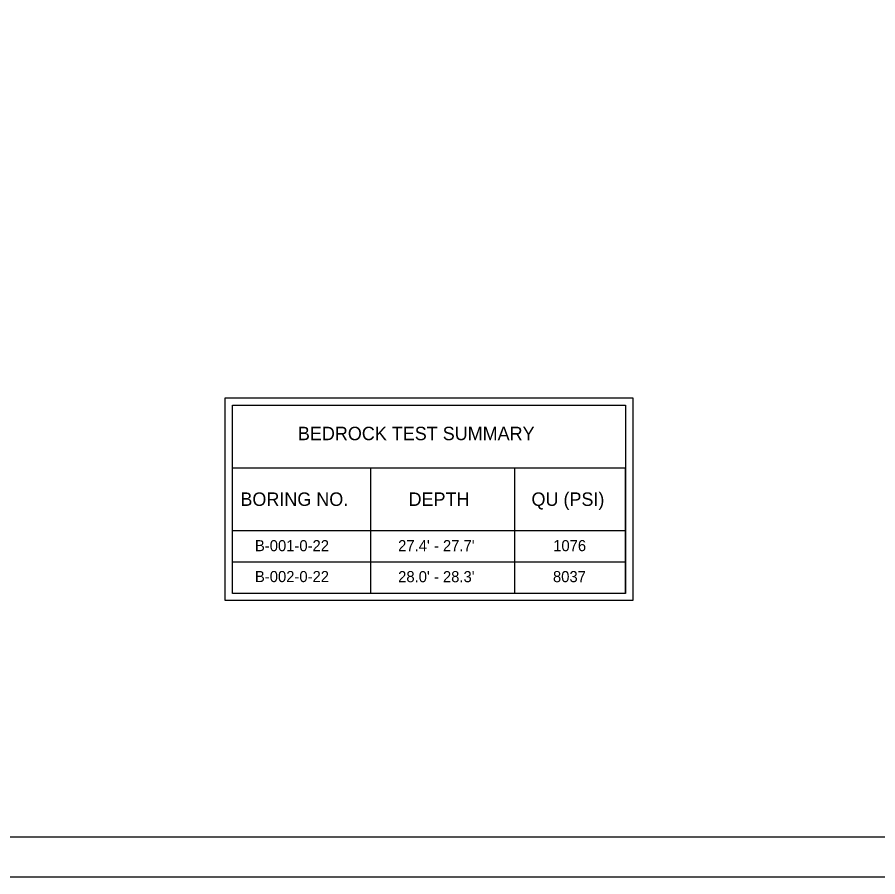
# Model space of a CAD drawing. Extents: x -60 to 375, y -195 to 44.
# Drawn here: x 6.18 to 11.62, y 0.02 to 5.46 of the extents above; entities that cross this region are included whole.
import ezdxf

# ---------------------------------------------------------------- set-up
doc = ezdxf.new("R2010")
doc.units = 0
for name, color, linetype in [('GM_X_County', 7, 'Continuous'), ('GM_X_County_Road_Text', 7, 'Continuous'), ('GM_X_Township_Road_Text', 7, 'Continuous')]:
    doc.layers.add(name, color=color, linetype=linetype)

msp = doc.modelspace()

# ---------------------------------------------------------------- linework, layer by layer
at = {"layer": 'GM_X_County'}
for p, q in [((7.4963, 3.0525), (10.0744, 3.0525)), ((7.4963, 1.7709), (7.4963, 3.0525)), ((10.0744, 3.0525), (10.0744, 1.7709)), ((7.5419, 3.0069), (10.0288, 3.0069)), ((7.5419, 1.8165), (7.5419, 3.0069)), ((10.0288, 3.0069), (10.0288, 1.8165)), ((7.5419, 2.6105), (10.0288, 2.6105)), ((8.4183, 1.8165), (8.4183, 2.6105)), ((8.4183, 1.8165), (8.4183, 2.6105)), ((9.3274, 1.8165), (9.3274, 2.6105)), ((10.0288, 1.8165), (10.0288, 2.6105)), ((7.5419, 2.2141), (10.0288, 2.2141)), ((7.5419, 2.0153), (10.0288, 2.0153)), ((7.4963, 1.7709), (7.4963, 1.8165)), ((10.0288, 1.8165), (7.5419, 1.8165)), ((7.5419, 1.8165), (7.5419, 1.8165)), ((10.0288, 1.8165), (10.0288, 1.8165)), ((10.0288, 1.8165), (10.0288, 1.8165)), ((10.0744, 1.8165), (10.0744, 1.7709)), ((10.0744, 1.7709), (7.4963, 1.7709))]:
    msp.add_line(p, q, dxfattribs=at)
at = {"layer": 'GM_X_County_Road_Text'}
msp.add_lwpolyline([(0.6151, 0.0249), (17.6151, 0.0249), (17.6151, 11.0249), (0.6151, 11.0249)], close=True, dxfattribs=at)
at = {"layer": 'GM_X_Township_Road_Text'}
msp.add_lwpolyline([(1.3651, 10.7749), (17.3651, 10.7749), (17.3651, 0.2749), (1.3651, 0.2749)], close=True, dxfattribs=at)

# ---------------------------------------------------------------- texts
for s, height, p in [('BEDROCK TEST SUMMARY', 0.085, (7.9562, 2.7852)), ('BORING NO.', 0.085, (7.5925, 2.3698)), ('DEPTH', 0.085, (8.656, 2.3698)), ('QU (PSI)', 0.085, (9.4334, 2.3698)), ('B-001-0-22', 0.07, (7.6845, 2.0833)), ("27.4' - 27.7'", 0.07, (8.5901, 2.0835)), ('1076', 0.07, (9.5706, 2.0835)), ('B-002-0-22', 0.07, (7.6845, 1.8881)), ("28.0' - 28.3'", 0.07, (8.5901, 1.8874)), ('8037', 0.07, (9.5692, 1.8875))]:
    msp.add_text(s, height=height, dxfattribs=at).set_placement(p)

doc.saveas('drawing.dxf')
